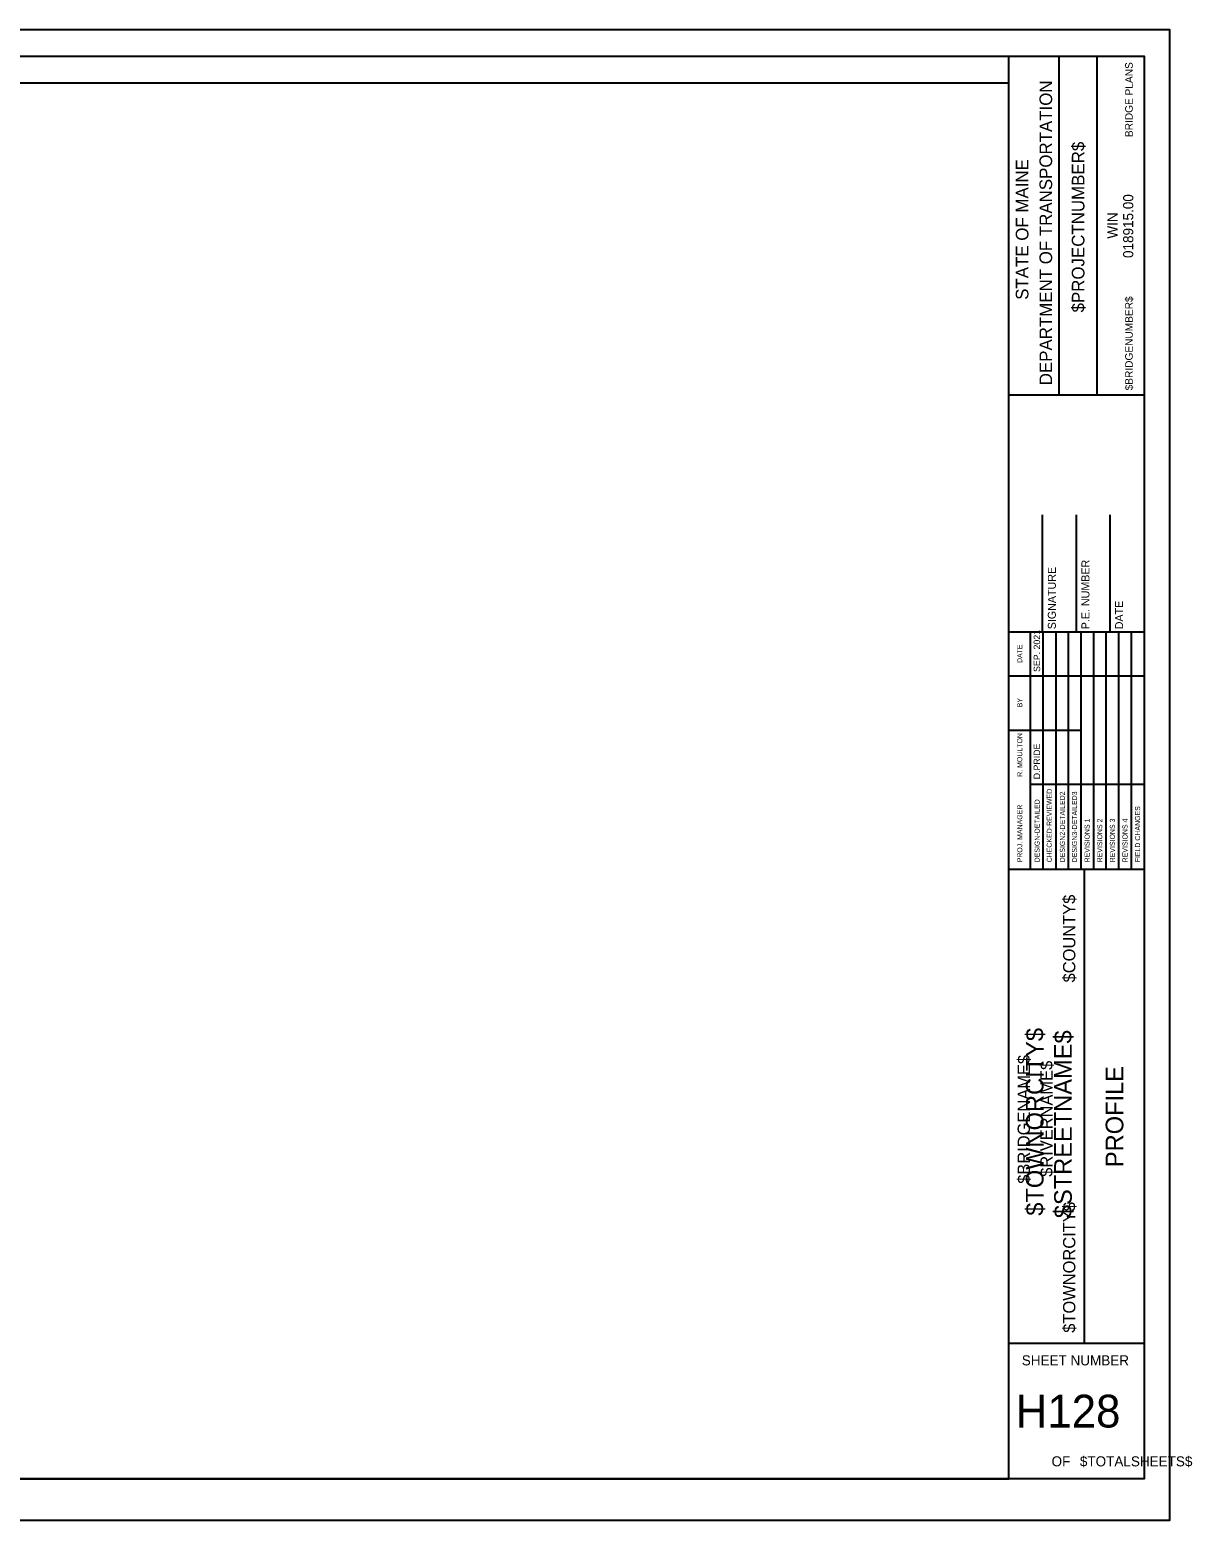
# Model space of a CAD drawing. Extents: x 9960 to 10818, y 9985 to 10535.
# Drawn here: x 10389 to 10818, y 9985 to 10535 of the extents above; entities that cross this region are included whole.
import ezdxf

# ---------------------------------------------------------------- set-up
doc = ezdxf.new("R2010")
doc.units = 0
for name, color, linetype in [('BORDER', 7, 'Continuous'), ('BRIDGE_TITLE', 7, 'Continuous'), ('CLIPS', 7, 'Continuous'), ('HIGHWAY_TITLE', 7, 'Continuous'), ('PLOT BOUNDARY', 7, 'Continuous')]:
    doc.layers.add(name, color=color, linetype=linetype)

msp = doc.modelspace()

# ---------------------------------------------------------------- linework, layer by layer
at = {"layer": 'BORDER'}
for p, q in [((10750, 10000), (10750, 10525)), ((10768.64, 10399.99), (10768.64, 10524.99)), ((10782.62, 10399.99), (10782.62, 10524.99)), ((10750, 10399.97), (10800, 10399.97)), ((10762.5, 10312.51), (10762.5, 10355.75)), ((10775, 10312.51), (10775, 10355.75)), ((10787.5, 10312.51), (10787.5, 10355.75)), ((10750, 10312.51), (10800, 10312.51)), ((10750, 10225.01), (10800, 10225.01)), ((10777.96, 10050.01), (10777.96, 10225.01)), ((10750, 10050.01), (10800, 10050.01))]:
    msp.add_line(p, q, dxfattribs=at)
msp.add_lwpolyline([(10000, 10525), (10800, 10525), (10800, 10000), (10000, 10000)], close=True, dxfattribs=at)
for points in [[(10758.07, 10296.26), (10758.07, 10312.51)], [(10762.74, 10225.03), (10762.74, 10312.51)], [(10767.4, 10312.51), (10767.4, 10225.03)], [(10772.05, 10225.03), (10772.05, 10312.51)], [(10776.71, 10225.03), (10776.71, 10312.51)], [(10781.37, 10225.03), (10781.37, 10312.51)], [(10786.03, 10225.03), (10786.03, 10312.51)], [(10790.69, 10225.03), (10790.69, 10312.51)], [(10795.35, 10225.03), (10795.35, 10312.51)], [(10758.08, 10225.03), (10758.08, 10308.98)], [(10750, 10296.26), (10800, 10296.26)], [(10750, 10276.26), (10758.08, 10276.26)], [(10758.07, 10276.26), (10776.71, 10276.26)], [(10758.07, 10256.26), (10800, 10256.26)]]:
    msp.add_lwpolyline(points, dxfattribs=at)
at = {"layer": 'CLIPS'}
msp.add_lwpolyline([(10000, 10000), (10750, 10000), (10750, 10515), (10000, 10515)], close=True, dxfattribs=at)
at = {"layer": 'PLOT BOUNDARY'}
msp.add_lwpolyline([(9959.53, 9984.7), (10809.53, 9984.7), (10809.53, 10534.7), (9959.53, 10534.7)], close=True, dxfattribs=at)

# ---------------------------------------------------------------- texts
at = {"layer": 'BORDER'}
for s, height, p in [('DEPARTMENT OF TRANSPORTATION', 4.6588, (10766.03, 10403.53)), ('$PROJECTNUMBER$', 4.6588, (10777.96, 10430.4)), ('STATE OF MAINE', 4.6588, (10757.28, 10435.06)), ('018915.00', 3.726, (10795.98, 10450.49)), ('WIN', 3.726, (10790.18, 10457.65)), ('SIGNATURE', 2.953, (10767.4, 10313.48)), ('P.E. NUMBER', 2.9528, (10779.8, 10313.48)), ('DATE', 2.953, (10792.21, 10313.48)), ('SEP. 2021', 2.423, (10761.61, 10297.74)), ('DATE', 1.857, (10755.02, 10301.04)), ('BY', 1.857, (10755.02, 10284.69)), ('R. MOULTON', 1.864, (10755.02, 10259.03)), ('D.PRIDE', 2.423, (10761.61, 10258.13)), ('CHECKED-REVIEWED', 1.8637, (10765.91, 10227.46)), ('DESIGN2-DETAILED2', 1.8637, (10770.75, 10227.46)), ('DESIGN3-DETAILED3', 1.8637, (10775.22, 10227.46)), ('PROJ. MANAGER', 1.8637, (10755.02, 10227.46)), ('DESIGN-DETAILED', 1.8637, (10761.43, 10227.46)), ('FIELD CHANGES', 1.8637, (10798.51, 10227.46)), ('REVISIONS 1', 1.8637, (10779.88, 10227.46)), ('REVISIONS 2', 1.8637, (10784.54, 10227.46)), ('REVISIONS 3', 1.8637, (10789.2, 10227.46)), ('REVISIONS 4', 1.8637, (10793.86, 10227.46)), ('PROFILE', 6.521, (10792.32, 10115))]:
    msp.add_text(s, height=height, rotation=90, dxfattribs=at).set_placement(p)
for s, height, p in [('SHEET NUMBER', 3.7264, (10754.83, 10041.83)), ('H128', 12.097, (10752.58, 10018.91)), ('OF', 3.726, (10765.83, 10004.56)), ('$TOTALSHEETS$', 3.7264, (10776.28, 10004.56))]:
    msp.add_text(s, height=height, dxfattribs=at).set_placement(p)
at = {"layer": 'BRIDGE_TITLE'}
for s, height, p in [('BRIDGE PLANS', 2.795, (10795.79, 10495.12)), ('$BRIDGENUMBER$', 2.795, (10795.79, 10401.65)), ('$COUNTY$', 4.536, (10774.6, 10183.17)), ('$BRIDGENAME$', 4.5358, (10757.83, 10108.86)), ('$RIVERNAME$', 4.5358, (10766.22, 10111.43)), ('$TOWNORCITY$', 4.5358, (10774.6, 10053.88))]:
    msp.add_text(s, height=height, rotation=90, dxfattribs=at).set_placement(p)
at = {"layer": 'HIGHWAY_TITLE'}
for s, p in [('$TOWNORCITY$', (10762.86, 10097.06)), ('$STREETNAME$', (10773.3, 10096.16))]:
    msp.add_text(s, height=6.5214, rotation=90, dxfattribs=at).set_placement(p)

doc.saveas('drawing.dxf')
